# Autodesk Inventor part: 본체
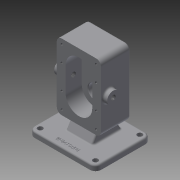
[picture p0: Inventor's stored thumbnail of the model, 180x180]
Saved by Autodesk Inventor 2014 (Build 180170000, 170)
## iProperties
Created: 2020-04
Part Number: 본체
Material: Generic
Document SubType Name: Modeling
Designer: kh
Density: 1 g/cm^3
Appearance: Default
Author: kh
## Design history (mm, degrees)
sketch "스케치1"
  geometry: L1 (-60, -50)-(60, -50); L2 (60, -50)-(60, 50); L3 (60, 50)-(-60, 50); L4 (-60, 50)-(-60, -50); L5 (-60, -50)-(60, 50); L6 (60, -50)-(-60, 50); 1 further point
  constraints: 12 end point, 2 midpoint, 2 parallel, 1 horizontal, 1 perpendicular
  dimensions: "d0" = 120 distance of L2.end L3.end; "d1" = 100 distance of L3.end L1.start
extrude "돌출1" new body sketch "스케치1" distance "d2" = 10; taper "d3" = 0 deg
node "작업 평면1"
sketch "스케치2"
  geometry: L1 (0, 0)-(120, 0) reference; L2 (120, 0)-(120, -10) reference; L3 (0, -10)-(120, -10) reference; L4 (0, 0)-(0, -10) reference; L5 (100, -150)-(20, -150); L6 (20, -150)-(20, -30); L7 (20, -30)-(100, -30); L8 (100, -30)-(100, -150); L9 (100, -90)-(20, -90); 3 further points
  constraints: 10 end point, 4 midpoint, 2 parallel, 1 horizontal, 1 perpendicular, 1 vertical alignment
  dimensions: "d5" = 90 distance between parallel lines of L9 L1; "d6" = 120 distance of L7.end L5.start; "d7" = 80 distance of L5.start L5.end
extrude "돌출2" join sketch "스케치2" distance "d8" = 53; taper "d9" = 0 deg
sketch "스케치3"
  geometry: L1 (100, -150)-(20, -150) reference; L2 (100, -30)-(100, -150) reference; L3 (20, -30)-(100, -30) reference; L4 (20, -150)-(20, -30) reference; L5 (120, 0)-(0, 0) reference; L6 (0, 0)-(0, -10) reference; L7 (120, -10)-(0, -10) reference; L8 (120, 0)-(120, -10) reference; L9 (100, -90)-(20, -90); C1 r 19 at (60, -112); 2 further points
  constraints: 3 midpoint, 2 end point, 1 centre point, 1 vertical alignment
  dimensions: "d10" = 22 distance from line of C1.centre L9; "d11" = 38 diameter of C1
extrude "돌출3" join sketch "스케치3" distance "d12" = 17; taper "d13" = 0 deg
sketch "스케치4"
  geometry: L1 (100, 150)-(20, 150) reference; L2 (20, 150)-(20, 30) reference; L3 (20, 30)-(100, 30) reference; L4 (100, 30)-(100, 150) reference; L5 (60, 112)-(60, 68); L6 (36, 112)-(36, 68); L7 (84, 68)-(84, 112); A1 r 24 centre (60, 112) between (84, 112) and (36, 112); A2 r 24 centre (60, 68) between (36, 68) and (84, 68); 4 further points
  constraints: 8 end point, 4 point on circle, 4 tangent, 3 midpoint, 2 centre point, 2 parallel, 1 horizontal alignment, 1 vertical alignment
  dimensions: "d14" = 92 dimension on A2 A1; "d16" = 22 distance of L5.start point (60, 90)
extrude "돌출4" cut sketch "스케치4" distance "d17" = 29; taper "d18" = 0 deg
sketch "스케치5"
  geometry: L1 (36, 68)-(36, 112) reference; L2 (84, 112)-(84, 68) reference; C1 r 19 at (60, 112) reference; C2 r 12.5 at (60, 112); C3 r 12.5 at (60, 68); A1 r 24 centre (60, 68) between (36, 68) and (84, 68) reference; A2 r 24 centre (60, 112) between (84, 112) and (36, 112) reference; 1 further point
  constraints: 2 centre point, 2 coincident, 1 equal radius
  dimensions: "d19" = 25 diameter of C2
extrude "돌출5" cut sketch "스케치5" distance "d20" = 15; taper "d21" = 0 deg
sketch "스케치6"
  geometry: C1 r 19 at (0, 0) reference; C2 r 14 at (0, 0); 1 further point
  constraints: 1 centre point, 1 coincident
  dimensions: "d22" = 28 diameter of C2
extrude "돌출6" cut sketch "스케치6" distance "d23" = 7.3; taper "d24" = 0 deg
sketch "스케치7"
  geometry: C1 r 14 at (0, 0) reference; C2 r 8.5 at (0, 0); 1 further point
  constraints: 1 centre point, 1 coincident
  dimensions: "d25" = 17 diameter of C2
extrude "돌출7" cut sketch "스케치7" stored distance "d26" = 7.3; taper "d27" = 0 deg
sketch "스케치8"
  geometry: L1 (120, 0)-(0, 0) reference; L2 (0, 0)-(0, -53) reference; L3 (120, -53)-(0, -53) reference; L4 (120, 0)-(120, -53) reference; L5 (150, -83)-(150, 17) reference; L6 (150, 17)-(140, 17) reference; L7 (140, -83)-(140, 17) reference; L8 (150, -83)-(140, -83) reference; C1 r 11 at (60, -39); 1 further point
  constraints: 1 centre point
  dimensions: "d28" = 22 diameter of C1; "d29" = 90 distance from line of C1.centre L5; "d30" = 14 distance from line of C1.centre L3
extrude "돌출8" join sketch "스케치8" distance "d31" = 8; taper "d32" = 0 deg
hole "구멍1" diameter "d35" = 8.376; stored, may be unused: countersink angle "d39" = 90 deg, drill point angle "d41" = 118 deg; dims "d33" = 10, "d34" = 10, "d36" = 6, "d37" = 4, "d38" = 2, "d40" = 8
sketch "스케치9"
  geometry: L1 (-44.03, -31.498)-(44.03, -31.498); L2 (44.03, -31.498)-(44.03, -48.502); L3 (44.03, -48.502)-(-44.03, -48.502); L4 (-44.03, -48.502)-(-44.03, -31.498); L5 (-44.03, -31.498)-(44.03, -48.502); L6 (44.03, -31.498)-(-44.03, -48.502); L7 (-60, 50)-(-60, -50) reference; L8 (-60, -50)-(60, -50) reference; 2 further points
  constraints: 4 end point, 1 midpoint, 2 other
  dimensions: "d42" = 60 distance from line of point (0, -40) L7; "d43" = 10 distance from line of point (0, -40) L8
feature "엠보싱1" sketch "스케치9" dims "d0" = 120, "d1" = 100, "d44" = 0.5, "d45" = 0
fillet "모깎기1" dims "d46" = 10
sketch "스케치10"
  geometry: L1 (-60, 40)-(-60, -40) reference; L2 (-50, -50)-(50, -50) reference; L3 (60, -40)-(60, 40) reference; L4 (50, 50)-(-50, 50) reference; L5 (15.014, -39.78)-(15.014, -41.089) reference; L6 (17.999, -40.885)-(18.046, -41.258) reference; L7 (14.566, -41.489)-(14.566, -37.86) reference; L8 (14.566, -37.86)-(17.463, -37.86) reference; L9 (17.463, -37.86)-(17.463, -38.233) reference; L10 (17.463, -38.233)-(15.014, -38.233) reference; L11 (15.014, -38.233)-(15.014, -39.406) reference; L12 (15.014, -39.406)-(17.198, -39.406) reference; L13 (17.198, -39.406)-(17.198, -39.78) reference; L14 (17.198, -39.78)-(15.014, -39.78) reference; L15 (12.449, -37.29)-(12.449, -41.666) reference; L16 (12.449, -41.666)-(11.995, -41.666) reference; L17 (11.995, -41.666)-(11.995, -37.079) reference; L18 (11.995, -37.079)-(12.354, -37.079) reference; L19 (11.289, -37.391)-(11.289, -41.415) reference; L20 (11.289, -41.415)-(10.834, -41.415) reference; L21 (10.834, -41.415)-(10.834, -38.993) reference; L22 (10.834, -38.993)-(9.803, -38.993) reference; L23 (9.803, -38.993)-(9.803, -38.647) reference; L24 (9.803, -38.647)-(10.834, -38.647) reference; L25 (10.834, -38.647)-(10.834, -37.154) reference; L26 (10.834, -37.154)-(11.208, -37.154) reference; L27 (12.592, -42.629)-(12.592, -43.002) reference; L28 (12.592, -43.002)-(8.27, -43.002) reference; L29 (8.27, -43.002)-(8.27, -41.089) reference; L30 (8.27, -41.089)-(8.602, -41.089) reference; L31 (8.718, -41.292)-(8.718, -42.629) reference; L32 (8.718, -42.629)-(12.592, -42.629) reference; L33 (10.414, -40.248)-(10.109, -40.594) reference; L34 (7.415, -40.797)-(7.103, -40.458) reference; L35 (8.67, -37.344)-(9.071, -37.344) reference; L36 (6.031, -40.98)-(6.479, -40.98) reference; L37 (6.438, -39.074)-(5.984, -39.074) reference; L38 (1.526, -37.615)-(1.526, -38.029) reference; L39 (1.526, -38.029)-(-0.034, -38.029) reference; L40 (-0.034, -38.029)-(-0.034, -42.615) reference; L41 (-0.034, -42.615)-(-0.488, -42.615) reference; L42 (-0.488, -42.615)-(-0.488, -38.029) reference; L43 (-0.488, -38.029)-(-2.042, -38.029) reference; L44 (-2.042, -38.029)-(-2.042, -37.615) reference; L45 (-2.042, -37.615)-(1.526, -37.615) reference; L46 (-10.095, -40.851)-(-8.284, -40.851) reference; L47 (-8.284, -40.851)-(-8.284, -42.975) reference; L48 (-8.284, -42.975)-(-8.745, -42.975) reference; L49 (-8.745, -42.975)-(-8.745, -41.225) reference; L50 (-8.745, -41.225)-(-12.578, -41.225) reference; L51 (-12.578, -41.225)-(-12.578, -40.851) reference; L52 (-12.578, -40.851)-(-10.55, -40.851) reference; L53 (-10.55, -40.851)-(-10.55, -39.63) reference; L54 (-10.55, -39.63)-(-13.311, -39.63) reference; L55 (-13.311, -39.63)-(-13.311, -39.257) reference; L56 (-13.311, -39.257)-(-8.942, -39.257) reference; L57 (-8.657, -37.588)-(-12.463, -37.588) reference; L58 (-12.463, -37.588)-(-12.463, -37.208) reference; L59 (-12.463, -37.208)-(-8.175, -37.208) reference; L60 (-8.446, -39.257)-(-7.307, -39.257) reference; L61 (-7.307, -39.257)-(-7.307, -39.63) reference; L62 (-7.307, -39.63)-(-10.095, -39.63) reference; L63 (-10.095, -39.63)-(-10.095, -40.851) reference; L64 (-2.917, -42.615)-(-3.474, -41.089) reference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; A1 r 10 centre (-50, 40) between (-50, 50) and (-60, 40) reference; A2 r 10 centre (-50, -40) between (-60, -40) and (-50, -50) reference; A3 r 10 centre (50, -40) between (50, -50) and (60, -40) reference; A4 r 10 centre (50, 40) between (60, 40) and (50, 50) reference; 58 further points
  constraints: 4 coincident, 68 other
hole "구멍2" sketch "스케치10" at (-50, 40), (-50, -40), (50, -40), (50, 40) diameter "d47" = 9; stored, may be unused: countersink angle "d51" = 90 deg, drill point angle "d53" = 118 deg; dims "d48" = 6, "d49" = 4, "d50" = 2, "d52" = 8
sketch "스케치11"
  geometry: L1 (36, 68)-(36, 112) reference; L2 (84, 112)-(84, 68) reference; L3 (100, 150)-(20, 150) reference; L4 (20, 150)-(20, 30) reference; L5 (20, 30)-(100, 30) reference; L6 (100, 30)-(100, 150) reference; L7 (20, 90)-(100, 90); L8 (60, 150)-(60, 30); L9 (29, 39)-(91, 39); L10 (91, 39)-(91, 141); L11 (91, 141)-(29, 141); L12 (29, 141)-(29, 39); L13 (29, 39)-(91, 141); L14 (91, 39)-(29, 141); L15 (29, 112)-(91, 112); L16 (29, 68)-(91, 68); A1 r 24 centre (60, 68) between (36, 68) and (84, 68) reference; A2 r 24 centre (60, 112) between (84, 112) and (36, 112) reference; 10 further points
  constraints: 20 end point, 8 coincident, 7 midpoint, 4 point on line, 3 parallel, 2 perpendicular, 1 horizontal
  dimensions: "d54" = 62 distance of L10.end L11.end; "d55" = 102 distance of L9.end L10.end; "d56" = 29 distance between parallel lines of L15 L11; "d57" = 44 distance between parallel lines of L16 L15
hole "구멍3" sketch "스케치11" at (29, 141), (29, 112), (29, 68), (29, 39), (91, 39), (91, 68), (91, 112), (91, 141) diameter "d58" = 4.134; stored, may be unused: countersink angle "d62" = 90 deg, drill point angle "d64" = 118 deg; dims "d59" = 10, "d60" = 4, "d61" = 2, "d63" = 12
fillet "모깎기2" dims "d65" = 9
sketch "스케치12"
  geometry: L1 (33, 30)-(-20, 30) reference; L2 (40, 10)-(-40, 10) reference; L3 (40, 10)-(50, 10) reference; L4 (50, 10)-(50, 0) reference; L5 (44.5, 0)-(35.5, 0) reference; L6 (50, 0)-(40, 0) reference; L7 (40, 0)-(-40, 0) reference; L8 (-35.5, 0)-(-44.5, 0) reference; L9 (-40, 0)-(-50, 0) reference; L10 (-50, 0)-(-50, 10) reference; L11 (-50, 10)-(-40, 10) reference; L12 (21.453, 30)-(33, 10); L13 (-8.453, 30)-(-20, 10); L14 (-20, 10)-(33, 10); L15 (-8.453, 30)-(21.453, 30); 1 further point
  constraints: 8 end point, 4 point on line, 1 collinear
  dimensions: "d66" = 17 horizontal distance of L12.end L4.end; "d67" = 60 deg angle of L2 L12; "d68" = 60 deg angle of L13 L2; "d69" = 53 distance of L13.end L12.end
extrude "돌출9" join sketch "스케치12" stored distance "d70" = 48; taper "d71" = 0 deg
chamfer "모따기1" distance "d72" = 0.7; stored, may be unused: second distance "d73" = 2, angle "d74" = 30 deg
fillet "모깎기3" dims "d75" = 0.5
chamfer "모따기2" distance "d76" = 1; stored, may be unused: second distance "d77" = 2, angle "d78" = 30 deg
fillet "모깎기4" dims "d79" = 3
fillet "모깎기5" dims "d80" = 3
fillet "모깎기6" dims "d81" = 3
node "솔리드1"
mirror "대칭1"
node "투영된 루프1"
node "투영된 루프2"
node "투영된 루프3"
node "투영된 루프4"
node "투영된 루프5"
node "투영된 루프6"
node "투영된 루프7"
node "투영된 루프8"
node "투영된 루프9"
node "투영된 루프10"
node "투영된 루프11"
other parameters: "d4" = -17
